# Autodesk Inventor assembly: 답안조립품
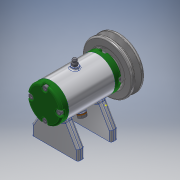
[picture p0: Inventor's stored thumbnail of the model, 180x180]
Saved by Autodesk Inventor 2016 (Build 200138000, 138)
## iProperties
Created: 2018-05
Part Number: 답안조립품
Material: 일반
Document SubType Name: Assembly
Designer: USER
Author: USER
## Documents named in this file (16)
- C:\Users\USER\Desktop\480507V1029\답안조립품.iam
- C:\Users\USER\Desktop\480507V1029\본체.ipt
- C:\Users\USER\Desktop\480507V1029\베어링 6002.ipt
- C:\Users\USER\Desktop\480507V1029\뒤커버.ipt
- C:\Users\USER\Desktop\480507V1029\앞커버.ipt
- C:\Users\USER\Desktop\480507V1029\오일 실 15 25 7.ipt
- C:\Users\USER\Desktop\480507V1029\축.ipt
- C:\Users\USER\Desktop\480507V1029\키 3x3x12.ipt
- C:\Users\USER\Desktop\480507V1029\V벨트풀리.ipt
- C:\Users\USER\Desktop\480507V1029\와셔 8x17.ipt
- C:\Users\USER\Desktop\480507V1029\스프링와셔 8.ipt
- C:\Users\USER\Desktop\480507V1029\너트 M8.ipt
- C:\Users\USER\Desktop\480507V1029\니플 M6x0.75.ipt
- C:\Users\USER\Desktop\480507V1029\와셔 6x11.5.ipt
- C:\Users\USER\Desktop\480507V1029\볼트 M6x8.ipt
- C:\Users\USER\Desktop\480507V1029\볼트 M4x12.ipt
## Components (1 placed, 1 different names)
1. V벨트풀리:1
